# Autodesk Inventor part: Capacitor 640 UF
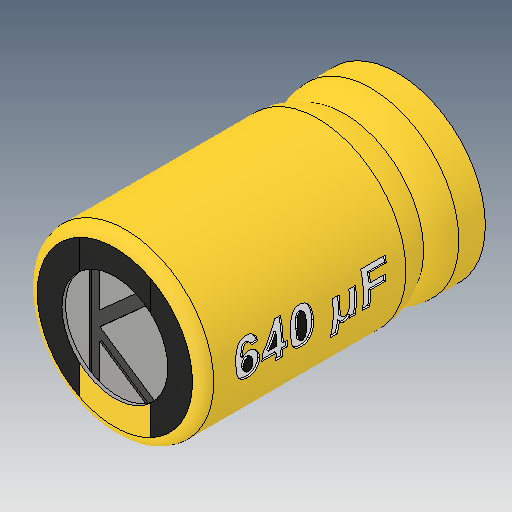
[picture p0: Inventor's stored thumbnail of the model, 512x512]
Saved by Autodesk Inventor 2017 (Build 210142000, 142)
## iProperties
Created: 2005-12
Part Number: Capacitor 640 UF
Material: Generic
Document SubType Name: Modeling
Designer: DanielSeverino
Density: 1 g/cm^3
Appearance: Default
Author: DanielSeverino
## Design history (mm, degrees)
feature "Solid1"
body "Solid2"
